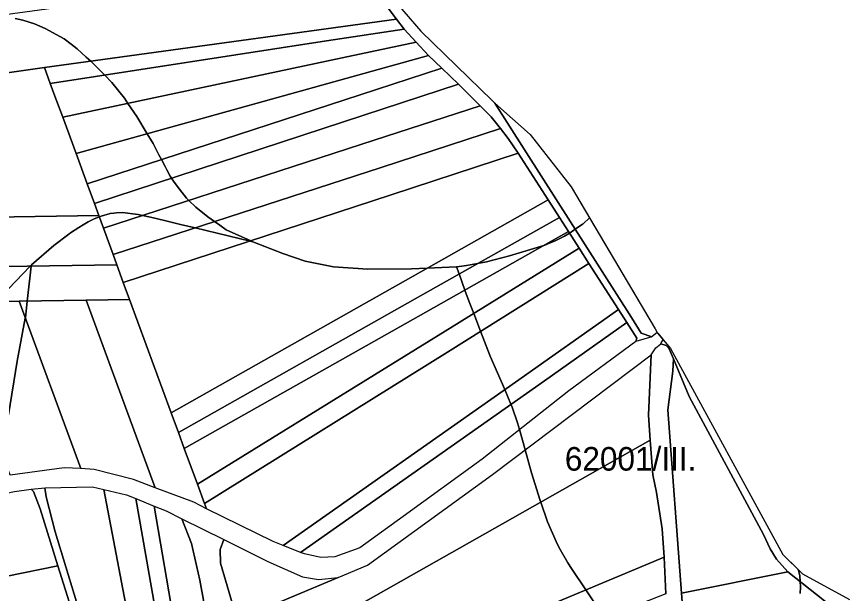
# Model space of a CAD drawing. Extents: x -521939 to -516426, y -1197857 to -1189551.
# Drawn here: x -518483 to -517954, y -1191399 to -1191032 of the extents above; entities that cross this region are included whole.
import ezdxf

# ---------------------------------------------------------------- set-up
doc = ezdxf.new("R2010")
doc.units = 0
for name, color, linetype in [('95560013', 7, 'Continuous'), ('95610013', 7, 'Continuous'), ('95630013', 7, 'Continuous'), ('95640013', 7, 'Continuous'), ('95660013', 7, 'Continuous')]:
    doc.layers.add(name, color=color, linetype=linetype)

msp = doc.modelspace()

# ---------------------------------------------------------------- linework, layer by layer
at = {"layer": '95560013'}
for points in [[(-518465.79, -1191064.52), (-518514.91, -1191071.43), (-518507.61, -1191054.38), (-518503.54, -1191049.96), (-518495.59, -1191031.42), (-518314.55, -1191006.68), (-518264.57, -1190999.85), (-518255.12, -1191016.14), (-518241.94, -1191033.87), (-518286.71, -1191040)], [(-518462.02, -1191074.79), (-518465.79, -1191064.52), (-518286.71, -1191040), (-518241.94, -1191033.87), (-518237.05, -1191040.06), (-518286.41, -1191047.68)], [(-518459.14, -1191082.65), (-518462.02, -1191074.79), (-518286.41, -1191047.68), (-518237.05, -1191040.06), (-518229.49, -1191048.48), (-518276.41, -1191058.44), (-518454.15, -1191096.17)], [(-518454.15, -1191096.17), (-518276.41, -1191058.44), (-518229.49, -1191048.48), (-518221.69, -1191056.99), (-518274.24, -1191071.6), (-518445.63, -1191119.25)], [(-518221.69, -1191056.99), (-518213.1, -1191065.02), (-518265.03, -1191081.92), (-518438.55, -1191138.39), (-518445.63, -1191119.25), (-518274.24, -1191071.6)], [(-518552.56, -1191160.42), (-518523.64, -1191091.67), (-518514.91, -1191071.43), (-518465.79, -1191064.52), (-518462.02, -1191074.79), (-518459.14, -1191082.65), (-518454.15, -1191096.17), (-518445.63, -1191119.25), (-518438.55, -1191138.39), (-518433.96, -1191150.84), (-518431.12, -1191158.54)], [(-518431.12, -1191158.54), (-518428.22, -1191166.6), (-518422.11, -1191183.44), (-518419.79, -1191189.87), (-518562.4, -1191192.05), (-518557.09, -1191173.61), (-518552.56, -1191160.42)], [(-518415.62, -1191201.18), (-518411.64, -1191211.98), (-518439.21, -1191212.42), (-518481.75, -1191213.09), (-518527.99, -1191213.82), (-518545.88, -1191214.1), (-518568.6, -1191214.46), (-518562.4, -1191192.05), (-518419.79, -1191189.87)], [(-518442.61, -1191319.4), (-518453.2, -1191318.84), (-518487.56, -1191323.54), (-518527.99, -1191213.82), (-518481.75, -1191213.09)], [(-518439.21, -1191212.42), (-518395.42, -1191331.64), (-518409.06, -1191326.28), (-518434.03, -1191319.91), (-518442.61, -1191319.4), (-518481.75, -1191213.09)], [(-518439.21, -1191212.42), (-518411.64, -1191211.98), (-518385.17, -1191283.98), (-518380.6, -1191296.42), (-518376.83, -1191306.69), (-518368.49, -1191329.37), (-518363.97, -1191341.66), (-518362.77, -1191344.93), (-518370.69, -1191340.74), (-518395.42, -1191331.64)]]:
    msp.add_lwpolyline(points, close=True, dxfattribs=at)
at = {"layer": '95610013'}
for points in [[(-518202.62, -1191075.2), (-518262.81, -1191094.88), (-518433.96, -1191150.84), (-518438.55, -1191138.39), (-518265.03, -1191081.92), (-518213.1, -1191065.02)], [(-518188.66, -1191088.83), (-518256.12, -1191110.73), (-518428.22, -1191166.6), (-518431.12, -1191158.54), (-518433.96, -1191150.84), (-518262.81, -1191094.88), (-518202.62, -1191075.2)], [(-518428.22, -1191166.6), (-518256.12, -1191110.73), (-518188.66, -1191088.83), (-518181.76, -1191095.94), (-518175.83, -1191103.36), (-518251.67, -1191128.02), (-518422.11, -1191183.44)], [(-518422.11, -1191183.44), (-518251.67, -1191128.02), (-518175.83, -1191103.36), (-518170.93, -1191109.62), (-518164.67, -1191118.91), (-518245.29, -1191145.34), (-518415.62, -1191201.18), (-518419.79, -1191189.87)], [(-518164.67, -1191118.91), (-518145.53, -1191148.62), (-518231.27, -1191197.05), (-518385.17, -1191283.98), (-518411.64, -1191211.98), (-518415.62, -1191201.18), (-518245.29, -1191145.34)], [(-518231.27, -1191197.05), (-518145.53, -1191148.62), (-518138.41, -1191159.77), (-518225.29, -1191208.79), (-518380.6, -1191296.42), (-518385.17, -1191283.98)], [(-518380.6, -1191296.42), (-518225.29, -1191208.79), (-518138.41, -1191159.77), (-518132.63, -1191168.76), (-518223.26, -1191219.95), (-518376.83, -1191306.69)], [(-518132.63, -1191168.76), (-518125.86, -1191179.32), (-518215.49, -1191234.75), (-518368.49, -1191329.37), (-518376.83, -1191306.69), (-518223.26, -1191219.95)], [(-518368.49, -1191329.37), (-518215.49, -1191234.75), (-518125.86, -1191179.32), (-518119.58, -1191189.13), (-518209.61, -1191245.32), (-518363.97, -1191341.66)], [(-518363.97, -1191341.66), (-518209.61, -1191245.32), (-518119.58, -1191189.13), (-518100.82, -1191218.36), (-518166.27, -1191264.4), (-518314.03, -1191368.34), (-518320.35, -1191365.76), (-518362.77, -1191344.93)], [(-518314.03, -1191368.34), (-518166.27, -1191264.4), (-518100.82, -1191218.36), (-518095.5, -1191226.66), (-518147.91, -1191263.54), (-518302.98, -1191372.66)], [(-518095.5, -1191226.66), (-518089.12, -1191236.6), (-518089.73, -1191238.72), (-518132.45, -1191270.05), (-518187.56, -1191313.35), (-518237.69, -1191349.9), (-518265.33, -1191369.69), (-518281.19, -1191375.52), (-518290.09, -1191375.94), (-518300.36, -1191373.65), (-518302.98, -1191372.66), (-518147.91, -1191263.54)], [(-518079.95, -1191247.19), (-518081.72, -1191285.53), (-518080.59, -1191301.43), (-518174.54, -1191354.51), (-518329.2, -1191441.89), (-518339.6, -1191413.97), (-518279.05, -1191388.52), (-518260.37, -1191380.66), (-518180.89, -1191323.09)], [(-518065.96, -1191249.61), (-518055.84, -1191273.59), (-518008.61, -1191361.3), (-518004.44, -1191370.41), (-518000.44, -1191376.9), (-517993.27, -1191384.91), (-518060.82, -1191398.45), (-518069.47, -1191282.08), (-518066.3, -1191257.46)], [(-518152.34, -1191409.28), (-518315.97, -1191477.51), (-518320.28, -1191465.56), (-518323.99, -1191455.76), (-518329.2, -1191441.89), (-518174.54, -1191354.51), (-518080.59, -1191301.43), (-518078.94, -1191323.44), (-518076.64, -1191334.54), (-518073.11, -1191357.72), (-518071.88, -1191375.73)], [(-518428, -1191332.68), (-518394.14, -1191510.49), (-518360.28, -1191688.3), (-518341.42, -1191787.34), (-518364.53, -1191790.38), (-518374.67, -1191707.44), (-518380.58, -1191707.99), (-518387.26, -1191657.11), (-518396.87, -1191613.34), (-518435.22, -1191438.67), (-518439.99, -1191421.45), (-518458.86, -1191359.62), (-518464.75, -1191337.42), (-518465.41, -1191331.65), (-518435.2, -1191331)], [(-518474.1, -1191332.51), (-518472.65, -1191333.85), (-518468.56, -1191344.96), (-518457.15, -1191381.15), (-518523.95, -1191394.84), (-518539.79, -1191345.38), (-518484.81, -1191334.03)], [(-518407.75, -1191338.3), (-518375.04, -1191524.34), (-518341.21, -1191716.75), (-518329.08, -1191785.74), (-518341.42, -1191787.34), (-518360.28, -1191688.3), (-518394.14, -1191510.49), (-518428, -1191332.68), (-518413.58, -1191336.14)], [(-518395.95, -1191343.18), (-518365.79, -1191520.03), (-518335.63, -1191696.88), (-518320.66, -1191784.66), (-518329.08, -1191785.74), (-518341.21, -1191716.75), (-518375.04, -1191524.34), (-518407.75, -1191338.3)], [(-518378.34, -1191351.41), (-518372.26, -1191367.06), (-518366.94, -1191390.2), (-518356.39, -1191448.17), (-518342, -1191480.43), (-518334.85, -1191506.3), (-518326.95, -1191566.18), (-518325.04, -1191593.59), (-518309.54, -1191691.73), (-518309.12, -1191719.22), (-518313.13, -1191742.82), (-518307.95, -1191783.04), (-518320.66, -1191784.66), (-518335.63, -1191696.88), (-518365.79, -1191520.03), (-518395.95, -1191343.18), (-518388.42, -1191346.21)], [(-518354, -1191370.72), (-518351.67, -1191364.52), (-518323.66, -1191378.34), (-518301.6, -1191388.22), (-518291.56, -1191389.89), (-518279.05, -1191388.52), (-518339.6, -1191413.97), (-518343.3, -1191415.51), (-518353.74, -1191379.46)], [(-518315.97, -1191477.51), (-518152.34, -1191409.28), (-518071.88, -1191375.73), (-518070.65, -1191398.87), (-518145.29, -1191428.18), (-518313.16, -1191494.1)], [(-518439.4, -1191439.86), (-518507.78, -1191452.68), (-518523.95, -1191394.84), (-518457.15, -1191381.15), (-518443.9, -1191423.5)], [(-517960.66, -1191410.53), (-518058.21, -1191431.96), (-518060.82, -1191398.45), (-517993.27, -1191384.91)]]:
    msp.add_lwpolyline(points, close=True, dxfattribs=at)
at = {"layer": '95630013'}
msp.add_lwpolyline([(-518157.01, -1191107.19), (-518130.99, -1191140.28), (-518077.55, -1191230.58), (-518076.18, -1191232.9), (-518079.58, -1191235.56), (-518086.45, -1191233.35), (-518092.5, -1191223.35), (-518179.38, -1191087.17)], close=True, dxfattribs=at)
msp.add_lwpolyline([(-518070.65, -1191398.87), (-518071.88, -1191375.73), (-518073.11, -1191357.72), (-518076.64, -1191334.54), (-518078.94, -1191323.44), (-518080.59, -1191301.43), (-518081.72, -1191285.53), (-518079.95, -1191247.19), (-518077.16, -1191242.55), (-518073.93, -1191240.12), (-518070.5, -1191241.25), (-518068.83, -1191242.94), (-518065.96, -1191249.61), (-518066.3, -1191257.46), (-518069.47, -1191282.08), (-518060.82, -1191398.45), (-518058.21, -1191431.96)], dxfattribs=at)
at = {"layer": '95640013'}
for points in [[(-518241.31, -1191024.36), (-518226.41, -1191041.52), (-518181.2, -1191085.54), (-518179.38, -1191087.17), (-518092.5, -1191223.35), (-518086.45, -1191233.35), (-518079.58, -1191235.56), (-518089.73, -1191238.72), (-518089.12, -1191236.6), (-518095.5, -1191226.66), (-518100.82, -1191218.36), (-518119.58, -1191189.13), (-518125.86, -1191179.32), (-518132.63, -1191168.76), (-518138.41, -1191159.77), (-518145.53, -1191148.62), (-518164.67, -1191118.91), (-518170.93, -1191109.62), (-518175.83, -1191103.36), (-518181.76, -1191095.94), (-518188.66, -1191088.83), (-518202.62, -1191075.2), (-518213.1, -1191065.02), (-518221.69, -1191056.99), (-518229.49, -1191048.48), (-518237.05, -1191040.06), (-518241.94, -1191033.87), (-518255.12, -1191016.14)], [(-518079.58, -1191235.56), (-518089.73, -1191238.72)], [(-518076.18, -1191232.9), (-518079.58, -1191235.56)], [(-518072.39, -1191237.51), (-518072.65, -1191237.19), (-518075.78, -1191233.39), (-518076.18, -1191232.9)], [(-518089.73, -1191238.72), (-518132.45, -1191270.05)], [(-518079.95, -1191247.19), (-518077.16, -1191242.55), (-518073.93, -1191240.12)], [(-517960.66, -1191410.53), (-517993.27, -1191384.91), (-518000.44, -1191376.9), (-518004.44, -1191370.41), (-518008.61, -1191361.3), (-518055.84, -1191273.59), (-518065.96, -1191249.61), (-518068.83, -1191242.94), (-518070.5, -1191241.25), (-518073.93, -1191240.12), (-518073.63, -1191239.4), (-518072.39, -1191237.51), (-518071.1, -1191239.08), (-518067.84, -1191243.04), (-517996.3, -1191374.01), (-517983.92, -1191386.29), (-517954.07, -1191402.48)], [(-518073.93, -1191240.12), (-518073.63, -1191239.4), (-518072.39, -1191237.51)], [(-518260.37, -1191380.66), (-518180.89, -1191323.09), (-518079.95, -1191247.19)], [(-518132.45, -1191270.05), (-518187.56, -1191313.35), (-518237.69, -1191349.9)], [(-518442.61, -1191319.4), (-518453.2, -1191318.84), (-518487.56, -1191323.54)], [(-518409.06, -1191326.28), (-518434.03, -1191319.91), (-518442.61, -1191319.4)], [(-518395.42, -1191331.64), (-518409.06, -1191326.28)], [(-518443.9, -1191423.5), (-518457.15, -1191381.15), (-518468.56, -1191344.96), (-518472.65, -1191333.85), (-518474.1, -1191332.51), (-518465.41, -1191331.65), (-518464.75, -1191337.42), (-518458.86, -1191359.62), (-518439.99, -1191421.45)], [(-518474.1, -1191332.51), (-518465.41, -1191331.65)], [(-518465.41, -1191331.65), (-518435.2, -1191331), (-518428, -1191332.68)], [(-518362.77, -1191344.93), (-518370.69, -1191340.74), (-518395.42, -1191331.64)], [(-518539.79, -1191345.38), (-518484.81, -1191334.03), (-518474.1, -1191332.51)], [(-518428, -1191332.68), (-518413.58, -1191336.14), (-518407.75, -1191338.3)], [(-518407.75, -1191338.3), (-518395.95, -1191343.18)], [(-518395.95, -1191343.18), (-518388.42, -1191346.21)], [(-518388.42, -1191346.21), (-518378.34, -1191351.41)], [(-518320.35, -1191365.76), (-518362.77, -1191344.93)], [(-518356.39, -1191448.17), (-518366.94, -1191390.2), (-518372.26, -1191367.06), (-518378.34, -1191351.41), (-518351.67, -1191364.52), (-518354, -1191370.72), (-518353.74, -1191379.46), (-518343.3, -1191415.51)], [(-518378.34, -1191351.41), (-518351.67, -1191364.52)], [(-518237.69, -1191349.9), (-518265.33, -1191369.69), (-518281.19, -1191375.52), (-518290.09, -1191375.94)], [(-518351.67, -1191364.52), (-518323.66, -1191378.34)], [(-518314.03, -1191368.34), (-518320.35, -1191365.76)], [(-518302.98, -1191372.66), (-518314.03, -1191368.34)], [(-518300.36, -1191373.65), (-518302.98, -1191372.66)], [(-518290.09, -1191375.94), (-518300.36, -1191373.65)], [(-518323.66, -1191378.34), (-518301.6, -1191388.22)], [(-518279.05, -1191388.52), (-518260.37, -1191380.66)], [(-518301.6, -1191388.22), (-518291.56, -1191389.89)], [(-518291.56, -1191389.89), (-518279.05, -1191388.52)]]:
    msp.add_lwpolyline(points, dxfattribs=at)
at = {"layer": '95660013'}
for points in [[(-518241.31, -1191024.36), (-518226.41, -1191041.52), (-518181.2, -1191085.54), (-518179.38, -1191087.17), (-518157.01, -1191107.19), (-518130.99, -1191140.28)], [(-518484.43, -1191033.47), (-518479.46, -1191034.53), (-518472.16, -1191036.73), (-518465.31, -1191039.73), (-518453.19, -1191046.28), (-518448.79, -1191049.65), (-518444.85, -1191052.66), (-518439.12, -1191057.93), (-518436.33, -1191060.49), (-518434.76, -1191061.93), (-518427.32, -1191069.43), (-518422.82, -1191073.98), (-518414.88, -1191084.01), (-518412.63, -1191087.36), (-518407, -1191095.72), (-518400.41, -1191106.68), (-518396.69, -1191112.87), (-518392.93, -1191119.99), (-518391.33, -1191123.02), (-518389.04, -1191127.36), (-518387.91, -1191129.49), (-518385.79, -1191133.5), (-518384.91, -1191134.8), (-518383.65, -1191136.66), (-518381.39, -1191140), (-518375.36, -1191147.53), (-518373.9, -1191148.96), (-518369.56, -1191153.21), (-518361.91, -1191159.35), (-518357.56, -1191162.45), (-518354.29, -1191164.78), (-518350.21, -1191167.7), (-518334.58, -1191174.61), (-518333.17, -1191175.23), (-518335.07, -1191174.77), (-518369.86, -1191166.45), (-518379.18, -1191164.22), (-518389.5, -1191161.79), (-518398.34, -1191159.7), (-518403.34, -1191158.52), (-518406.19, -1191157.85), (-518416.04, -1191156.69), (-518419.98, -1191156.92), (-518421.53, -1191157.1), (-518423.93, -1191157.38), (-518429.61, -1191158.89), (-518430.81, -1191159.39), (-518434.1, -1191160.77), (-518435.79, -1191161.61), (-518437.86, -1191162.63), (-518441.15, -1191164.5), (-518443.95, -1191166.1), (-518449.14, -1191169.61), (-518450.21, -1191170.34), (-518459.77, -1191177.58), (-518474.03, -1191189.98), (-518474.73, -1191190.71), (-518493.04, -1191209.8)], [(-518130.99, -1191140.28), (-518119.04, -1191160.48), (-518119.3, -1191160.04), (-518123.22, -1191163.78), (-518123.63, -1191164.13), (-518128.28, -1191167.26), (-518131.63, -1191169.52), (-518132, -1191169.74), (-518135.19, -1191171.64), (-518141.48, -1191174.86), (-518144.25, -1191176), (-518147.71, -1191177.43), (-518148.29, -1191177.6), (-518170.08, -1191184.16), (-518184.69, -1191188.1), (-518190.35, -1191189.08), (-518197.44, -1191190.3), (-518200.33, -1191190.68), (-518203.78, -1191191.14), (-518222.37, -1191192.02), (-518232.44, -1191192.5), (-518260.14, -1191192.73), (-518282.05, -1191191.11), (-518299.9, -1191187.52), (-518314.27, -1191182.65), (-518333.17, -1191175.23), (-518334.58, -1191174.61), (-518350.21, -1191167.7), (-518354.29, -1191164.78), (-518357.56, -1191162.45), (-518361.91, -1191159.35), (-518369.56, -1191153.21), (-518373.9, -1191148.96), (-518375.36, -1191147.53), (-518381.39, -1191140), (-518383.65, -1191136.66), (-518384.91, -1191134.8), (-518385.79, -1191133.5), (-518387.91, -1191129.49), (-518389.04, -1191127.36), (-518391.33, -1191123.02), (-518392.93, -1191119.99), (-518396.69, -1191112.87), (-518400.41, -1191106.68), (-518407, -1191095.72), (-518412.63, -1191087.36), (-518414.88, -1191084.01), (-518422.82, -1191073.98), (-518427.32, -1191069.43), (-518434.76, -1191061.93), (-518436.33, -1191060.49), (-518439.12, -1191057.93), (-518444.85, -1191052.66), (-518448.79, -1191049.65), (-518453.19, -1191046.28), (-518465.31, -1191039.73), (-518472.16, -1191036.73), (-518479.46, -1191034.53), (-518484.43, -1191033.47)], [(-518488.69, -1191285.2), (-518483.01, -1191251.13), (-518477.91, -1191223.77), (-518477.89, -1191223.58), (-518476.68, -1191213.01), (-518474.99, -1191198.34), (-518474.11, -1191190.7), (-518474.03, -1191189.98), (-518459.77, -1191177.58), (-518450.21, -1191170.34), (-518449.14, -1191169.61), (-518443.95, -1191166.1), (-518441.15, -1191164.5), (-518437.86, -1191162.63), (-518435.79, -1191161.61), (-518434.1, -1191160.77), (-518430.81, -1191159.39), (-518429.61, -1191158.89), (-518423.93, -1191157.38), (-518421.53, -1191157.1), (-518419.98, -1191156.92), (-518416.04, -1191156.69), (-518406.19, -1191157.85), (-518403.34, -1191158.52), (-518398.34, -1191159.7), (-518389.5, -1191161.79), (-518379.18, -1191164.22), (-518369.86, -1191166.45), (-518335.07, -1191174.77), (-518333.17, -1191175.23), (-518314.27, -1191182.65), (-518299.9, -1191187.52), (-518282.05, -1191191.11), (-518260.14, -1191192.73), (-518232.44, -1191192.5), (-518222.37, -1191192.02), (-518203.78, -1191191.14), (-518202.11, -1191195.71), (-518198.4, -1191205.91), (-518195.67, -1191213.4), (-518192.84, -1191220.75), (-518188.47, -1191232.12), (-518182.34, -1191248.05), (-518173.07, -1191269.15), (-518169.17, -1191278.5), (-518168.43, -1191280.28), (-518164.95, -1191290.25), (-518163.73, -1191294.63), (-518161.47, -1191302.76), (-518160.16, -1191307.5), (-518156.14, -1191322), (-518150.58, -1191339.62), (-518150.19, -1191340.76), (-518145.94, -1191353.3), (-518140.35, -1191365.76), (-518138.76, -1191369.3), (-518132.96, -1191379.26), (-518130.61, -1191382.81), (-518121.58, -1191396.45), (-518121.14, -1191397.12), (-518109.8, -1191414.24)], [(-518109.8, -1191414.24), (-518121.14, -1191397.12), (-518121.58, -1191396.45), (-518130.61, -1191382.81), (-518132.96, -1191379.26), (-518138.76, -1191369.3), (-518140.35, -1191365.76), (-518145.94, -1191353.3), (-518150.19, -1191340.76), (-518150.58, -1191339.62), (-518156.14, -1191322), (-518160.16, -1191307.5), (-518161.47, -1191302.76), (-518163.73, -1191294.63), (-518164.95, -1191290.25), (-518168.43, -1191280.28), (-518169.17, -1191278.5), (-518173.07, -1191269.15), (-518182.34, -1191248.05), (-518188.47, -1191232.12), (-518192.84, -1191220.75), (-518195.67, -1191213.4), (-518198.4, -1191205.91), (-518202.11, -1191195.71), (-518203.78, -1191191.14), (-518200.33, -1191190.68), (-518197.44, -1191190.3), (-518190.35, -1191189.08), (-518184.69, -1191188.1), (-518170.08, -1191184.16), (-518148.29, -1191177.6), (-518147.71, -1191177.43), (-518144.25, -1191176), (-518141.48, -1191174.86), (-518135.19, -1191171.64), (-518132, -1191169.74), (-518131.63, -1191169.52), (-518128.28, -1191167.26), (-518123.63, -1191164.13), (-518123.22, -1191163.78), (-518119.3, -1191160.04), (-518119.04, -1191160.48), (-518077.55, -1191230.58), (-518076.18, -1191232.9), (-518075.78, -1191233.39), (-518072.65, -1191237.19), (-518072.39, -1191237.51), (-518071.1, -1191239.08), (-518067.84, -1191243.04), (-517996.3, -1191374.01), (-517986.67, -1191383.56)], [(-518493.04, -1191209.8), (-518474.73, -1191190.71), (-518474.03, -1191189.98), (-518474.11, -1191190.7), (-518474.99, -1191198.34), (-518476.68, -1191213.01), (-518477.89, -1191223.58), (-518477.91, -1191223.77), (-518483.01, -1191251.13), (-518488.69, -1191285.2)], [(-517986.67, -1191383.56), (-517986.02, -1191385.66), (-517985.52, -1191387.61), (-517985.31, -1191391.16), (-517985.12, -1191394.51), (-517985.29, -1191398.68)], [(-517986.67, -1191383.56), (-517983.92, -1191386.29), (-517954.07, -1191402.48)], [(-517985.29, -1191398.68), (-517985.12, -1191394.51), (-517985.31, -1191391.16), (-517985.52, -1191387.61), (-517986.02, -1191385.66), (-517986.67, -1191383.56)]]:
    msp.add_lwpolyline(points, dxfattribs=at)

# ---------------------------------------------------------------- texts
msp.add_text('62001/III.', height=15, rotation=360, dxfattribs=at).set_placement((-518134.95, -1191320.69))

doc.saveas('drawing.dxf')
